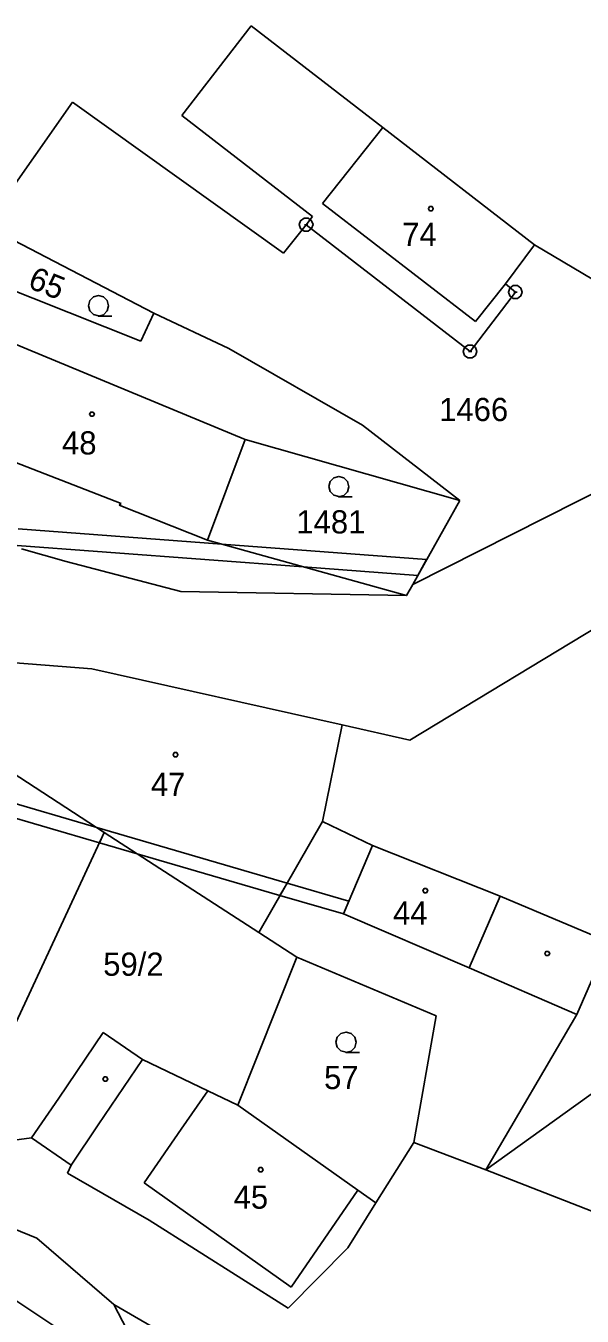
# Model space of a CAD drawing. Extents: x -850689 to -847910, y -1058374 to -1054747.
# Drawn here: x -849167.4 to -849126.6, y -1056250.1 to -1056155.5 of the extents above; entities that cross this region are included whole.
import ezdxf

# ---------------------------------------------------------------- set-up
doc = ezdxf.new("R2010")
doc.units = 0
for name, color, linetype in [('KN_BREMENA', 7, 'Continuous'), ('KN_HRANICE', 7, 'Continuous'), ('KN_KULTURY', 7, 'Continuous'), ('KN_MEZNIKY', 7, 'Continuous'), ('KN_PARCELY', 7, 'Continuous'), ('KN_SLUCKY', 7, 'Continuous'), ('KN_STAVEBNI', 7, 'Continuous')]:
    doc.layers.add(name, color=color, linetype=linetype)

# ---------------------------------------------------------------- blocks, each defined once
blk = doc.blocks.new('304')
blk.add_lwpolyline([(0, 0), (-0.38, 0.1), (-0.65, 0.37), (-0.75, 0.74), (-0.65, 1.11), (-0.38, 1.38), (-0.01, 1.48), (0.36, 1.38), (0.63, 1.11), (0.73, 0.73), (0.63, 0.35), (0.36, 0.08), (-0.02, -0.02), (0.98, -0.02)])
blk = doc.blocks.new('NAHRADNI_SYMBOL')
blk.add_lwpolyline([(0.09, 0.15), (0.18, 0), (0.09, -0.15), (-0.09, -0.15), (-0.18, 0), (-0.09, 0.15), (0.09, 0.15)])
blk = doc.blocks.new('402')
blk.add_lwpolyline([(0.09, 0.15), (0.18, 0), (0.09, -0.15), (-0.09, -0.15), (-0.18, 0), (-0.09, 0.15), (0.09, 0.15)])
blk = doc.blocks.new('105')
blk.add_line((-0.12, 0), (0.12, 0))
blk.add_lwpolyline([(0.15, 0.48), (0.4, 0.3), (0.5, 0.01), (0.4, -0.28), (0.15, -0.46), (-0.16, -0.46), (-0.41, -0.28), (-0.51, 0.01), (-0.41, 0.3), (-0.16, 0.48), (0.15, 0.48)])

msp = doc.modelspace()

# ---------------------------------------------------------------- linework, layer by layer
at = {"layer": 'KN_BREMENA'}
for points in [[(-849167.93, -1056192.39), (-849153, -1056193.52), (-849137.98, -1056194.65), (-849138.63, -1056195.81), (-849147.02, -1056195.18), (-849168.67, -1056193.56), (-849169.32, -1056193.41), (-849179.61, -1056189.36)], [(-849169.34, -1056212.19), (-849162.17, -1056214.28), (-849161.61, -1056214.65), (-849161.96, -1056215.41), (-849169.66, -1056213.16), (-849178.11, -1056228.14), (-849181.45, -1056234.05), (-849182.44, -1056233.76)]]:
    msp.add_lwpolyline(points, dxfattribs=at)
for points in [[(-849162.17, -1056214.28), (-849148.21, -1056218.37), (-849148.73, -1056219.27), (-849159.2, -1056216.21), (-849161.61, -1056214.65)], [(-849159.2, -1056216.21), (-849161.96, -1056215.41), (-849161.61, -1056214.65)], [(-849144.08, -1056220.62), (-849148.73, -1056219.27), (-849148.21, -1056218.37), (-849143.68, -1056219.69)]]:
    msp.add_lwpolyline(points, close=True, dxfattribs=at)
at = {"layer": 'KN_HRANICE'}
for p, q in [((-849155.93, -1056162.08), (-849150.85, -1056155.51)), ((-849150.85, -1056155.51), (-849141.2, -1056162.97)), ((-849163.93, -1056161.11), (-849170.31, -1056170.18)), ((-849148.47, -1056172.18), (-849163.93, -1056161.11)), ((-849146.34, -1056169.48), (-849155.93, -1056162.08)), ((-849141.2, -1056162.97), (-849130.07, -1056171.57)), ((-849157.98, -1056176.57), (-849170.31, -1056170.18)), ((-849146.81, -1056170.1), (-849148.47, -1056172.18)), ((-849146.81, -1056170.1), (-849146.34, -1056169.48)), ((-849134.79, -1056179.4), (-849146.81, -1056170.1)), ((-849130.07, -1056171.57), (-849132.2, -1056174.42)), ((-849122.32, -1056176.18), (-849130.07, -1056171.57)), ((-849171.71, -1056173.55), (-849158.94, -1056178.64)), ((-849132.2, -1056174.42), (-849131.47, -1056175.04)), ((-849131.47, -1056175.04), (-849134.79, -1056179.4)), ((-849158.94, -1056178.64), (-849157.98, -1056176.57)), ((-849152.47, -1056179.17), (-849157.98, -1056176.57)), ((-849142.67, -1056184.79), (-849152.47, -1056179.17)), ((-849139, -1056196.47), (-849111.09, -1056182.39)), ((-849135.54, -1056190.32), (-849142.67, -1056184.79)), ((-849151.28, -1056185.84), (-849154.04, -1056193.23)), ((-849135.54, -1056190.32), (-849151.28, -1056185.84)), ((-849139.2, -1056207.88), (-849107.15, -1056188.47)), ((-849139, -1056196.47), (-849135.54, -1056190.32)), ((-849164.4, -1056194.78), (-849167.69, -1056193.85)), ((-849154.04, -1056193.23), (-849139.45, -1056197.27)), ((-849164.4, -1056194.78), (-849156.01, -1056196.98)), ((-849139.45, -1056197.27), (-849139, -1056196.47)), ((-849156.01, -1056196.98), (-849139.45, -1056197.27)), ((-849168.44, -1056202.2), (-849162.53, -1056202.65)), ((-849162.53, -1056202.65), (-849144.18, -1056206.76)), ((-849145.61, -1056213.86), (-849144.18, -1056206.76)), ((-849144.18, -1056206.76), (-849139.2, -1056207.88)), ((-849171.3, -1056208.37), (-849161.61, -1056214.65)), ((-849172.06, -1056237.11), (-849161.61, -1056214.65)), ((-849161.61, -1056214.65), (-849150.29, -1056221.98)), ((-849150.29, -1056221.98), (-849145.61, -1056213.86)), ((-849141.96, -1056215.62), (-849145.61, -1056213.86)), ((-849132.6, -1056219.32), (-849141.96, -1056215.62)), ((-849124.65, -1056222.67), (-849132.6, -1056219.32)), ((-849150.29, -1056221.98), (-849147.5, -1056223.79)), ((-849126.97, -1056227.99), (-849124.65, -1056222.67)), ((-849151.82, -1056234.65), (-849147.5, -1056223.79)), ((-849137.29, -1056228.1), (-849147.5, -1056223.79)), ((-849138.93, -1056237.39), (-849137.29, -1056228.1)), ((-849133.63, -1056239.4), (-849126.97, -1056227.99)), ((-849164.95, -1056234.13), (-849161.69, -1056229.33)), ((-849161.69, -1056229.33), (-849158.8, -1056231.3)), ((-849158.8, -1056231.3), (-849154.03, -1056233.59)), ((-849154.03, -1056233.59), (-849151.82, -1056234.65)), ((-849133.63, -1056239.4), (-849125.31, -1056233.41)), ((-849166.94, -1056237.05), (-849164.95, -1056234.13)), ((-849151.82, -1056234.65), (-849143.03, -1056240.87)), ((-849170.59, -1056237.53), (-849166.94, -1056237.05)), ((-849164.05, -1056239.04), (-849166.94, -1056237.05)), ((-849138.93, -1056237.39), (-849141.7, -1056241.81)), ((-849138.93, -1056237.39), (-849133.63, -1056239.4)), ((-849164.31, -1056239.64), (-849164.05, -1056239.04)), ((-849158.31, -1056243.07), (-849164.31, -1056239.64)), ((-849133.63, -1056239.4), (-849123.4, -1056243.38)), ((-849143.03, -1056240.87), (-849141.7, -1056241.81)), ((-849166.56, -1056244.39), (-849174.51, -1056241.18)), ((-849141.7, -1056241.81), (-849143.76, -1056245.1)), ((-849148.13, -1056249.54), (-849158.31, -1056243.07)), ((-849160.92, -1056249.26), (-849166.56, -1056244.39)), ((-849172.85, -1056245.8), (-849164.8, -1056251.16)), ((-849143.76, -1056245.1), (-849148.13, -1056249.54)), ((-849158.72, -1056253.46), (-849160.92, -1056249.26)), ((-849160.92, -1056249.26), (-849150.75, -1056255.14))]:
    msp.add_line(p, q, dxfattribs=at)
at = {"layer": 'KN_SLUCKY'}
for p, q in [((-849145.62, -1056168.53), (-849141.2, -1056162.97)), ((-849134.39, -1056177.2), (-849145.62, -1056168.53)), ((-849132.2, -1056174.42), (-849134.39, -1056177.2)), ((-849151.28, -1056185.84), (-849171.52, -1056177.46)), ((-849174.47, -1056185.05), (-849160.38, -1056190.53)), ((-849160.38, -1056190.53), (-849160.53, -1056190.66)), ((-849160.53, -1056190.66), (-849154.04, -1056193.23)), ((-849141.96, -1056215.62), (-849144.08, -1056220.62)), ((-849134.87, -1056224.59), (-849132.6, -1056219.32)), ((-849144.08, -1056220.62), (-849134.87, -1056224.59)), ((-849134.87, -1056224.59), (-849126.97, -1056227.99)), ((-849158.8, -1056231.3), (-849162.06, -1056236.09)), ((-849155.97, -1056236.4), (-849154.03, -1056233.59)), ((-849164.05, -1056239.04), (-849162.06, -1056236.09)), ((-849158.69, -1056240.35), (-849155.97, -1056236.4)), ((-849147.9, -1056247.99), (-849158.69, -1056240.35)), ((-849143.03, -1056240.87), (-849147.9, -1056247.99))]:
    msp.add_line(p, q, dxfattribs=at)
at = {"layer": 'KN_STAVEBNI'}
for p, q in [((-849145.62, -1056168.53), (-849141.2, -1056162.97)), ((-849141.2, -1056162.97), (-849130.07, -1056171.57)), ((-849134.39, -1056177.2), (-849145.62, -1056168.53)), ((-849130.07, -1056171.57), (-849132.2, -1056174.42)), ((-849132.2, -1056174.42), (-849134.39, -1056177.2)), ((-849151.28, -1056185.84), (-849171.52, -1056177.46)), ((-849174.47, -1056185.05), (-849160.38, -1056190.53)), ((-849151.28, -1056185.84), (-849154.04, -1056193.23)), ((-849160.38, -1056190.53), (-849160.53, -1056190.66)), ((-849160.53, -1056190.66), (-849154.04, -1056193.23)), ((-849141.96, -1056215.62), (-849144.08, -1056220.62)), ((-849132.6, -1056219.32), (-849141.96, -1056215.62)), ((-849134.87, -1056224.59), (-849132.6, -1056219.32)), ((-849144.08, -1056220.62), (-849134.87, -1056224.59)), ((-849155.97, -1056236.4), (-849154.03, -1056233.59)), ((-849154.03, -1056233.59), (-849151.82, -1056234.65)), ((-849151.82, -1056234.65), (-849143.03, -1056240.87)), ((-849158.69, -1056240.35), (-849155.97, -1056236.4)), ((-849147.9, -1056247.99), (-849158.69, -1056240.35)), ((-849143.03, -1056240.87), (-849147.9, -1056247.99))]:
    msp.add_line(p, q, dxfattribs=at)

# ---------------------------------------------------------------- block references
at = {"layer": 'KN_KULTURY'}
for name, p in [('402', (-849137.67, -1056168.92)), ('304', (-849162.03, -1056176.77)), ('402', (-849162.52, -1056183.98)), ('304', (-849144.41, -1056190.03)), ('NAHRADNI_SYMBOL', (-849156.39, -1056208.95)), ('402', (-849138.08, -1056218.92)), ('402', (-849129.14, -1056223.52)), ('304', (-849143.88, -1056230.77)), ('402', (-849161.53, -1056232.73)), ('402', (-849150.15, -1056239.38))]:
    msp.add_blockref(name, p, dxfattribs=at)
at = {"layer": 'KN_MEZNIKY'}
for p in [(-849146.81, -1056170.1), (-849131.47, -1056175.04), (-849134.79, -1056179.4)]:
    msp.add_blockref('105', p, dxfattribs=at)

# ---------------------------------------------------------------- texts
at = {"layer": 'KN_PARCELY'}
for s, p in [('74', (-849139.77, -1056171.65)), ('1466', (-849137.06, -1056184.49)), ('48', (-849164.709, -1056186.94)), ('1481', (-849147.527, -1056192.73)), ('47', (-849158.199, -1056211.98)), ('44', (-849140.44, -1056221.41)), ('59/2', (-849161.689, -1056225.16)), ('57', (-849145.499, -1056233.47)), ('45', (-849152.129, -1056242.24))]:
    msp.add_text(s, height=1.7, dxfattribs=at).set_placement(p)
msp.add_text('65', height=1.7, rotation=337.931, dxfattribs=at).set_placement((-849167.298, -1056174.686))

doc.saveas('drawing.dxf')
